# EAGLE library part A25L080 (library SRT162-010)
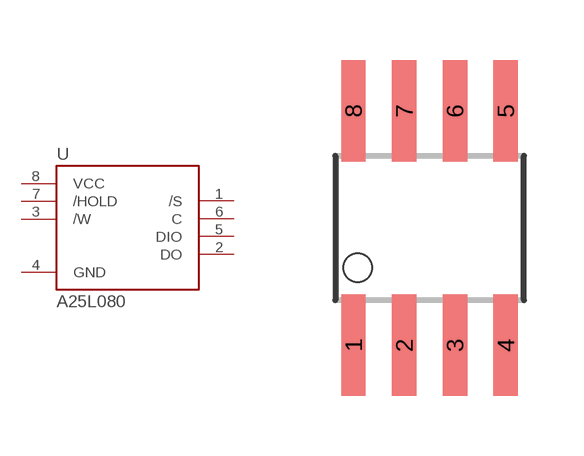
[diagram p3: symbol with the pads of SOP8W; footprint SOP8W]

Designator prefix U

## A25L080  [SOP8W]
1  /S  in
2  DO
3  /W  in
4  GND  pwr
5  DIO
6  C
7  /HOLD  in
8  VCC  in

## Footprint SOP8W (pad centres in mm)
smd 0.61 x 2.54: 1 -1.905,-2.934; 2 -0.635,-2.934; 3 0.635,-2.934; 4 1.905,-2.934; 5 1.905,2.934; 6 0.635,2.934; 7 -0.635,2.934; 8 -1.905,2.934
